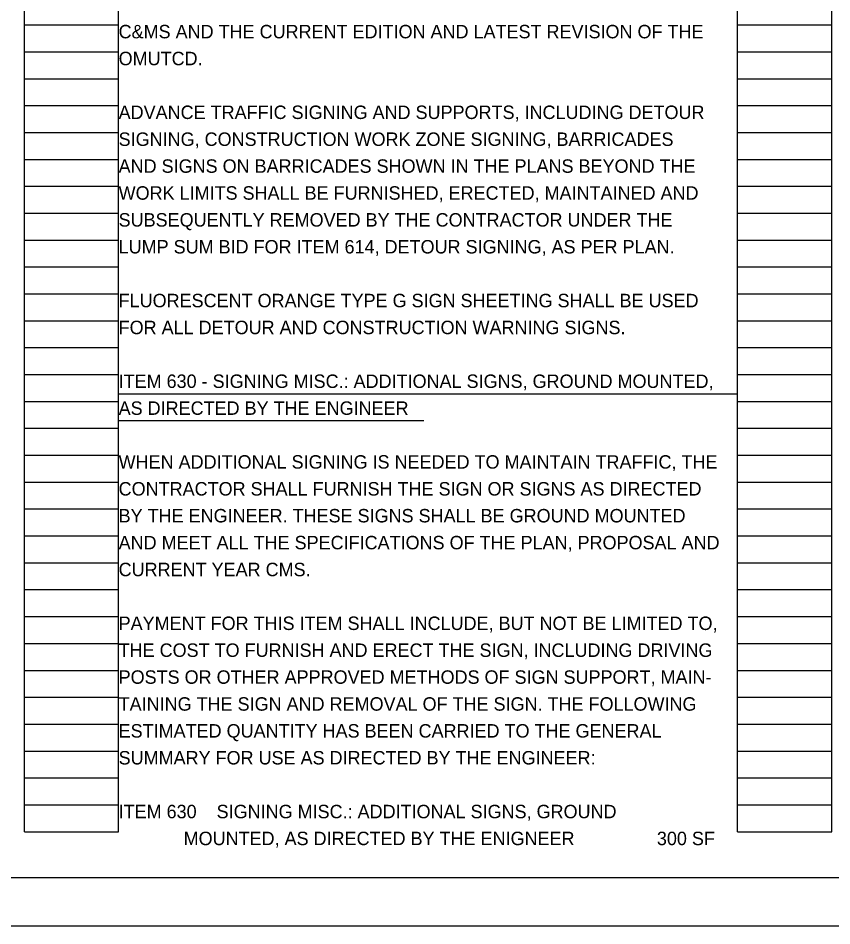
# Model space of a CAD drawing. Extents: x 0 to 34, y 0 to 22.
# Drawn here: x 16.19 to 24.66, y 0 to 9.45 of the extents above; entities that cross this region are included whole.
import ezdxf

# ---------------------------------------------------------------- set-up
doc = ezdxf.new("R2010")
doc.units = 0
for name, color, linetype in [('SH_Border', 7, 'Continuous'), ('SH_Cut_Line', 7, 'Continuous'), ('SH_Data', 7, 'Continuous'), ('SH_Text', 7, 'Continuous')]:
    doc.layers.add(name, color=color, linetype=linetype)

msp = doc.modelspace()

# ---------------------------------------------------------------- linework, layer by layer
at = {"layer": 'SH_Border'}
msp.add_lwpolyline([(1.5, 21.5), (33.5, 21.5), (33.5, 0.5), (1.5, 0.5)], close=True, dxfattribs=at)
at = {"layer": 'SH_Cut_Line'}
msp.add_lwpolyline([(0, 0), (34, 0), (34, 22), (0, 22)], close=True, dxfattribs=at)
at = {"layer": 'SH_Data'}
for p, q in [((16.26, 0.98), (16.26, 21.14)), ((17.24, 0.98), (17.24, 21.14)), ((23.68, 0.98), (23.68, 21.14)), ((24.66, 0.98), (24.66, 21.14)), ((16.26, 9.38), (17.24, 9.38)), ((23.68, 9.38), (24.66, 9.38)), ((16.26, 9.1), (17.24, 9.1)), ((23.68, 9.1), (24.66, 9.1)), ((16.26, 8.82), (17.24, 8.82)), ((23.68, 8.82), (24.66, 8.82)), ((16.26, 8.54), (17.24, 8.54)), ((23.68, 8.54), (24.66, 8.54)), ((16.26, 8.26), (17.24, 8.26)), ((23.68, 8.26), (24.66, 8.26)), ((16.26, 7.98), (17.24, 7.98)), ((23.68, 7.98), (24.66, 7.98)), ((16.26, 7.7), (17.24, 7.7)), ((23.68, 7.7), (24.66, 7.7)), ((16.26, 7.42), (17.24, 7.42)), ((23.68, 7.42), (24.66, 7.42)), ((16.26, 7.14), (17.24, 7.14)), ((23.68, 7.14), (24.66, 7.14)), ((16.26, 6.86), (17.24, 6.86)), ((23.68, 6.86), (24.66, 6.86)), ((16.26, 6.58), (17.24, 6.58)), ((23.68, 6.58), (24.66, 6.58)), ((16.26, 6.3), (17.24, 6.3)), ((23.68, 6.3), (24.66, 6.3)), ((16.26, 6.02), (17.24, 6.02)), ((23.68, 6.02), (24.66, 6.02)), ((16.26, 5.74), (17.24, 5.74)), ((23.68, 5.74), (24.66, 5.74)), ((16.26, 5.46), (17.24, 5.46)), ((23.68, 5.46), (24.66, 5.46)), ((16.26, 5.18), (17.24, 5.18)), ((23.68, 5.18), (24.66, 5.18)), ((16.26, 4.9), (17.24, 4.9)), ((23.68, 4.9), (24.66, 4.9)), ((16.26, 4.62), (17.24, 4.62)), ((23.68, 4.62), (24.66, 4.62)), ((16.26, 4.34), (17.24, 4.34)), ((23.68, 4.34), (24.66, 4.34)), ((16.26, 4.06), (17.24, 4.06)), ((23.68, 4.06), (24.66, 4.06)), ((16.26, 3.78), (17.24, 3.78)), ((23.68, 3.78), (24.66, 3.78)), ((16.26, 3.5), (17.24, 3.5)), ((23.68, 3.5), (24.66, 3.5)), ((16.26, 3.22), (17.24, 3.22)), ((23.68, 3.22), (24.66, 3.22)), ((16.26, 2.94), (17.24, 2.94)), ((23.68, 2.94), (24.66, 2.94)), ((16.26, 2.66), (17.24, 2.66)), ((23.68, 2.66), (24.66, 2.66)), ((16.26, 2.38), (17.24, 2.38)), ((23.68, 2.38), (24.66, 2.38)), ((16.26, 2.1), (17.24, 2.1)), ((23.68, 2.1), (24.66, 2.1)), ((16.26, 1.82), (17.24, 1.82)), ((23.68, 1.82), (24.66, 1.82)), ((16.26, 1.54), (17.24, 1.54)), ((23.68, 1.54), (24.66, 1.54)), ((16.26, 1.26), (17.24, 1.26)), ((23.68, 1.26), (24.66, 1.26)), ((16.26, 0.98), (17.24, 0.98)), ((23.68, 0.98), (24.66, 0.98))]:
    msp.add_line(p, q, dxfattribs=at)
at = {"layer": 'SH_Text'}
for p, q in [((17.24, 5.54), (23.68, 5.54)), ((17.24, 5.26), (20.4145, 5.26))]:
    msp.add_line(p, q, dxfattribs=at)

# ---------------------------------------------------------------- texts
for s, p in [('C&MS AND THE CURRENT EDITION AND LATEST REVISION OF THE ', (17.24, 9.24)), ('OMUTCD.', (17.24, 8.96)), ('ADVANCE TRAFFIC SIGNING AND SUPPORTS, INCLUDING DETOUR ', (17.24, 8.4)), ('SIGNING, CONSTRUCTION WORK ZONE SIGNING, BARRICADES ', (17.24, 8.12)), ('AND SIGNS ON BARRICADES SHOWN IN THE PLANS BEYOND THE ', (17.24, 7.84)), ('WORK LIMITS SHALL BE FURNISHED, ERECTED, MAINTAINED AND ', (17.24, 7.56)), ('SUBSEQUENTLY REMOVED BY THE CONTRACTOR UNDER THE ', (17.24, 7.28)), ('LUMP SUM BID FOR ITEM 614, DETOUR SIGNING, AS PER PLAN.', (17.24, 7)), ('FLUORESCENT ORANGE TYPE G SIGN SHEETING SHALL BE USED ', (17.24, 6.44)), ('FOR ALL DETOUR AND CONSTRUCTION WARNING SIGNS.', (17.24, 6.16)), ('ITEM 630 - SIGNING MISC.: ADDITIONAL SIGNS, GROUND MOUNTED,', (17.24, 5.6)), ('AS DIRECTED BY THE ENGINEER', (17.24, 5.32)), ('WHEN ADDITIONAL SIGNING IS NEEDED TO MAINTAIN TRAFFIC, THE', (17.24, 4.76)), ('CONTRACTOR SHALL FURNISH THE SIGN OR SIGNS AS DIRECTED', (17.24, 4.48)), ('BY THE ENGINEER. THESE SIGNS SHALL BE GROUND MOUNTED', (17.24, 4.2)), ('AND MEET ALL THE SPECIFICATIONS OF THE PLAN, PROPOSAL AND', (17.24, 3.92)), ('CURRENT YEAR CMS.', (17.24, 3.64)), ('PAYMENT FOR THIS ITEM SHALL INCLUDE, BUT NOT BE LIMITED TO,', (17.24, 3.08)), ('THE COST TO FURNISH AND ERECT THE SIGN, INCLUDING DRIVING', (17.24, 2.8)), ('POSTS OR OTHER APPROVED METHODS OF SIGN SUPPORT, MAIN-', (17.24, 2.52)), ('TAINING THE SIGN AND REMOVAL OF THE SIGN. THE FOLLOWING', (17.24, 2.24)), ('ESTIMATED QUANTITY HAS BEEN CARRIED TO THE GENERAL', (17.24, 1.96)), ('SUMMARY FOR USE AS DIRECTED BY THE ENGINEER:', (17.24, 1.68)), ('ITEM 630    SIGNING MISC.: ADDITIONAL SIGNS, GROUND', (17.24, 1.12)), ('             MOUNTED, AS DIRECTED BY THE ENIGNEER', (17.24, 0.84)), ('300 SF', (22.84, 0.84))]:
    msp.add_text(s, height=0.14, dxfattribs=at).set_placement(p)

doc.saveas('drawing.dxf')
